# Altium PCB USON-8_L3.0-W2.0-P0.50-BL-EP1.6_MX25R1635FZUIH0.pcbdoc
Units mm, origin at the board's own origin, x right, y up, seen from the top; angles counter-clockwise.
Board outline 15.04 x 16.1 mm, 2 copper layers (Top Layer, Bottom Layer), stack 0 mm thick; 1 components, 0 nets, 9 pads, 0 vias.
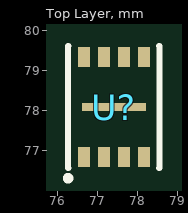
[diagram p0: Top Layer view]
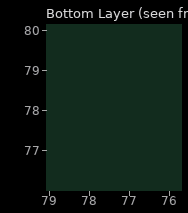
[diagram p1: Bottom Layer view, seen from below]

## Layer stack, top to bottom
Top Layer: signal copper (thickness not stored)
Bottom Layer: signal copper (thickness not stored)

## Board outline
84.893,69.85 69.85,69.85 69.85,85.952 84.893,85.952

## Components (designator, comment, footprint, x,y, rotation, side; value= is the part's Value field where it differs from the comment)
U? "" USON-8_L3.0-W2.0-P0.50-BL-EP1.6_MX25R1635FZUIH0 77.4,78.078 r0 top

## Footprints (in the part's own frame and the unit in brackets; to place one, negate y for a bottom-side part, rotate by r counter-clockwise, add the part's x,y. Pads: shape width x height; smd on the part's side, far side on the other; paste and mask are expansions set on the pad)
USON-8_L3.0-W2.0-P0.50-BL-EP1.6_MX25R1635FZUIH0 [mm]
  rect 0.3x0.5 smd paste+0 mask+0.05: 1(-0.75,-1.25) 2(-0.25,-1.25) 3(0.25,-1.25) 4(0.75,-1.25) 5(0.75,1.25) 6(0.25,1.25) 7(-0.25,1.25) 8(-0.75,1.25)
  rect 1.6x0.2 smd paste+0 mask+0.05: 9(0,0)
  silkscreen extent -1.2,-1.83 1.14,1.52

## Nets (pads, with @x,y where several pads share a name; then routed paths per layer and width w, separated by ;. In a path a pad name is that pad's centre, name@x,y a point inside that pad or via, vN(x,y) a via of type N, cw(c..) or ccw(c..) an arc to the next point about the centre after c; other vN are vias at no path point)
pads on no net: U?.1 U?.2 U?.3 U?.4 U?.5 U?.6 U?.7 U?.8 U?.9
